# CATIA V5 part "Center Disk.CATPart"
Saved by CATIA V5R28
Part number: Center Disk
Material "Beige": density 7860 kg/m3, Young's modulus 2e+11 Pa, Poisson ratio 0.266
Bounding box of the stored display mesh (mm): x -36 to 36, y 0 to 27, z -35.991 to 35.991
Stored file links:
  C:\Users\Parisa\Desktop\tarah sanat\Oldham Coupling\Center Disk.CATPart
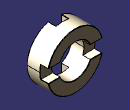
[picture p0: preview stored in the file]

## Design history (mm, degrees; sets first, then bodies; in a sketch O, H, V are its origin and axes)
Body1 (main body), material "Beige"
  Sketch1 on zx-plane, origin (0, 0, 0), H (-1, 0, 0), V (0, 0, 1)
    circle A1 centre (0, 0) radius 21.25
    circle A2 centre (0, 0) radius 36
    radius A2 = 36
    radius A1 = 21.25
  Pad1: profile Sketch1, direction (0, 1, 0), length 27
  Sketch2 on start face of Pad1, origin (0, 0, 0), H (1, 0, 0), V (0, 0, 1)
    line L1 (8.25, 36) -> (8.25, -36)
    line L2 (8.25, -36) -> (-8.25, -36)
    line L3 (-8.25, -36) -> (-8.25, 36)
    line L4 (-8.25, 36) -> (8.25, 36)
    reference projected circle E1 centre (0, 0) radius 36 from edge [start face of Pad1 | face of Pad1 from Sketch1.A2]
    distance L1 L3 = 16.5
    vertical: L1 V, L3 V
    horizontal: L2 H, L4 H
    equidistance: L1 L3 O, L2 L4 O
    tangency: L4 E1
  Pocket1: profile Sketch2, direction (0, 1, 0), length 10
  Sketch3 on end face of Pad1, origin (0, 27, 0), H (-1, 0, 0), V (0, 0, 1)
    line L1 (36, 8.25) -> (36, -8.25)
    line L2 (36, -8.25) -> (-36, -8.25)
    line L3 (-36, -8.25) -> (-36, 8.25)
    line L4 (-36, 8.25) -> (36, 8.25)
    reference projected circle E1 centre (0, 0) radius 36 from edge [face of Pad1 from Sketch1.A2 | end face of Pad1]
    distance L4 L2 = 16.5
    vertical: L1 V, L3 V
    horizontal: L2 H, L4 H
    equidistance: L1 L3 O, L2 L4 O
    tangency: L1 E1
  Pocket2: profile Sketch3, direction (0, -1, 0), length 10
  Chamfer1: length 0.5, angle 45, on end face of Pad1 (x2); face of Pad1 from Sketch1.A2; start face of Pad1 (x2)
